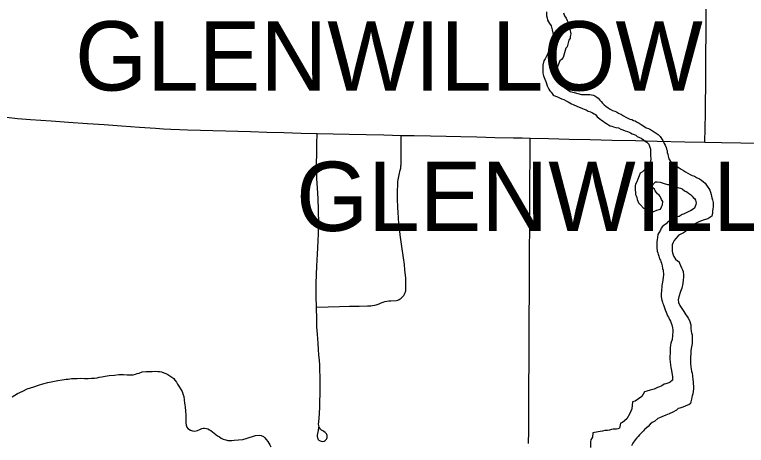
# Model space of a CAD drawing. Extents: x 0 to 34, y 0 to 22.
# Drawn here: x 6.666 to 7.666, y 15.413 to 16.002 of the extents above; entities that cross this region are included whole.
import ezdxf

# ---------------------------------------------------------------- set-up
doc = ezdxf.new("R2010")
doc.units = 0
for name, color, linetype in [('GM_X_City_Street', 7, 'Continuous'), ('GM_X_Corporation_Text', 7, 'Continuous'), ('GM_X_County_Road', 7, 'Continuous'), ('GM_X_Minor_River', 7, 'Continuous')]:
    doc.layers.add(name, color=color, linetype=linetype)

msp = doc.modelspace()

# ---------------------------------------------------------------- linework, layer by layer
at = {"layer": 'GM_X_City_Street'}
for points in [[(7.0813, 15.4379), (7.0805, 15.4333), (7.0797, 15.4293), (7.0794, 15.4273), (7.0793, 15.4257), (7.0796, 15.4234), (7.0801, 15.4223), (7.0807, 15.4213), (7.0815, 15.4204), (7.0825, 15.4197), (7.0835, 15.4192), (7.0846, 15.4188), (7.087, 15.4187), (7.0887, 15.4191), (7.0902, 15.42), (7.0911, 15.4208), (7.0919, 15.4217), (7.0924, 15.4228), (7.0928, 15.4239), (7.0929, 15.4245), (7.093, 15.4256), (7.0928, 15.4269), (7.0925, 15.428), (7.0919, 15.4291), (7.0912, 15.4301), (7.09, 15.431), (7.0882, 15.432), (7.0868, 15.4329), (7.0853, 15.4339), (7.0839, 15.4353), (7.0821, 15.4379), (7.0815, 15.4401), (7.0813, 15.4426), (7.0814, 15.4447), (7.0823, 15.4566), (7.0828, 15.4652), (7.0831, 15.4709), (7.0834, 15.486), (7.0833, 15.5071), (7.083, 15.5159), (7.0827, 15.5228), (7.0823, 15.5297), (7.0817, 15.5366), (7.0811, 15.5445), (7.0805, 15.5524), (7.0796, 15.5653), (7.0793, 15.5703), (7.079, 15.5752), (7.0788, 15.5802), (7.0786, 15.5851), (7.0782, 15.6023), (7.078, 15.6172), (7.0781, 15.6346), (7.0785, 15.6469), (7.0788, 15.6583), (7.0796, 15.6744), (7.0808, 15.6925), (7.0811, 15.7032), (7.0814, 15.7161), (7.0812, 15.7347), (7.0806, 15.7509), (7.0797, 15.7647), (7.0789, 15.778), (7.0787, 15.7831), (7.0785, 15.7996), (7.0786, 15.811), (7.079, 15.8251), (7.0792, 15.8396)], [(7.0782, 15.6023), (7.0945, 15.6026), (7.1098, 15.603), (7.1237, 15.6033), (7.1369, 15.6035), (7.1479, 15.6038), (7.1525, 15.604), (7.1551, 15.6043), (7.1576, 15.6047), (7.16, 15.6054), (7.1626, 15.6062), (7.164, 15.6067), (7.1667, 15.6079), (7.1693, 15.6089), (7.1719, 15.6097), (7.1746, 15.6103), (7.1774, 15.6107), (7.1802, 15.611), (7.1877, 15.6114), (7.1895, 15.6119), (7.1912, 15.6126), (7.1927, 15.6134), (7.1941, 15.6144), (7.1954, 15.6156), (7.1966, 15.6169), (7.1976, 15.6182), (7.1985, 15.6197), (7.1993, 15.6213), (7.1999, 15.6229), (7.2003, 15.6246), (7.2006, 15.6263), (7.2007, 15.6282), (7.2006, 15.6341), (7.2003, 15.6416), (7.1993, 15.653), (7.1986, 15.6603), (7.1975, 15.6694), (7.1952, 15.6852), (7.1929, 15.701), (7.1917, 15.7107), (7.1913, 15.7145), (7.1909, 15.7183), (7.1906, 15.7222), (7.1903, 15.726), (7.19, 15.7298), (7.1895, 15.7402), (7.1893, 15.7485), (7.1893, 15.7614), (7.1894, 15.7696), (7.1895, 15.7717), (7.1898, 15.7739), (7.1902, 15.776), (7.1916, 15.7829), (7.1929, 15.7895), (7.1932, 15.7908), (7.1935, 15.7923), (7.1937, 15.7937), (7.1939, 15.7952), (7.194, 15.7967), (7.194, 15.7981), (7.194, 15.837)], [(7.3685, 15.4159), (7.3686, 15.4328), (7.3687, 15.4557), (7.3688, 15.4748), (7.3689, 15.5001), (7.369, 15.5224), (7.3691, 15.5465), (7.3692, 15.5695), (7.3694, 15.5942), (7.3695, 15.6158), (7.3696, 15.6367), (7.3697, 15.6626), (7.3698, 15.6852), (7.3699, 15.7059), (7.3701, 15.7291), (7.3702, 15.7542), (7.3703, 15.7785), (7.3704, 15.8023), (7.3706, 15.8332)]]:
    msp.add_lwpolyline(points, dxfattribs=at)
at = {"layer": 'GM_X_County_Road'}
for points in [[(7.6096, 15.8275), (7.6099, 15.847), (7.6102, 15.8671), (7.6104, 15.884), (7.6106, 15.9018), (7.6107, 15.9168), (7.6108, 15.9264), (7.6109, 15.9342), (7.611, 15.954), (7.6112, 15.97), (7.6113, 15.986), (7.6114, 15.9993), (7.6114, 16.0097)], [(6.6543, 15.862), (6.6695, 15.8601), (6.6874, 15.8588), (6.7155, 15.8569), (6.7393, 15.8552), (6.7651, 15.8534), (6.788, 15.8518), (6.8116, 15.8501), (6.8365, 15.8484), (6.8583, 15.8468), (6.8691, 15.8461), (6.8793, 15.8455), (6.891, 15.8449), (6.902, 15.8445), (6.9198, 15.844), (6.9365, 15.8436), (6.9542, 15.8431), (6.9706, 15.8426), (6.9882, 15.8421), (7.0103, 15.8415), (7.0336, 15.8409), (7.0573, 15.8402), (7.0792, 15.8396), (7.1013, 15.8391), (7.1231, 15.8386), (7.1461, 15.8381), (7.1705, 15.8376), (7.194, 15.837), (7.2117, 15.8367), (7.2344, 15.8362), (7.2556, 15.8357), (7.2756, 15.8353), (7.2974, 15.8348), (7.3223, 15.8343), (7.3476, 15.8337), (7.3596, 15.8335)], [(7.3596, 15.8335), (7.3706, 15.8332), (7.3954, 15.8326), (7.4238, 15.832), (7.4526, 15.8313), (7.4825, 15.8305), (7.5148, 15.8298), (7.5443, 15.8291), (7.5819, 15.8282), (7.6096, 15.8275), (7.6321, 15.8271), (7.6587, 15.8267), (7.6839, 15.8263)]]:
    msp.add_lwpolyline(points, dxfattribs=at)
at = {"layer": 'GM_X_Minor_River'}
for points in [[(7.393, 16.0059), (7.393, 16.0006), (7.3938, 15.9976), (7.3941, 15.9945), (7.3957, 15.9923), (7.3972, 15.99), (7.3991, 15.9869), (7.4006, 15.9812), (7.4029, 15.971), (7.4029, 15.9679), (7.4014, 15.9649), (7.3999, 15.9611), (7.3983, 15.9569), (7.3964, 15.9543), (7.3957, 15.9516), (7.3945, 15.9489), (7.3934, 15.9463), (7.3911, 15.9417), (7.3892, 15.9387), (7.3881, 15.933), (7.3877, 15.9311), (7.3877, 15.9284), (7.3877, 15.9254), (7.3881, 15.922), (7.3889, 15.9182), (7.3896, 15.9159), (7.3904, 15.914), (7.3919, 15.9106), (7.3927, 15.9079), (7.3938, 15.9049), (7.3949, 15.903), (7.3961, 15.9003), (7.3976, 15.898), (7.3991, 15.8961), (7.4006, 15.8942), (7.4022, 15.8919), (7.4052, 15.8904), (7.4079, 15.8897), (7.4105, 15.8882), (7.4136, 15.887), (7.4166, 15.8859), (7.4197, 15.8844), (7.4227, 15.8828), (7.425, 15.8817), (7.4273, 15.8802), (7.4295, 15.8794), (7.4345, 15.8771), (7.4421, 15.8737), (7.4444, 15.873), (7.447, 15.8718), (7.4501, 15.8703), (7.4531, 15.8692), (7.4558, 15.8677), (7.4581, 15.8665), (7.46, 15.8654), (7.4622, 15.8623), (7.466, 15.8597), (7.4683, 15.8578), (7.4706, 15.8563), (7.4725, 15.8547), (7.4748, 15.8532), (7.4778, 15.8513), (7.4801, 15.8502), (7.4824, 15.8494), (7.4847, 15.8487), (7.4877, 15.8479), (7.4915, 15.8471), (7.4946, 15.8456), (7.4972, 15.8445), (7.5006, 15.8433), (7.5037, 15.8422), (7.506, 15.8415), (7.5079, 15.8403), (7.5101, 15.8392), (7.5128, 15.8384), (7.5151, 15.8373), (7.517, 15.8354), (7.52, 15.8339), (7.5223, 15.8331), (7.5254, 15.8308), (7.528, 15.8289), (7.5299, 15.8278), (7.533, 15.8251), (7.5341, 15.8209), (7.5349, 15.8183)], [(7.4162, 16.0044), (7.4177, 16.0003), (7.4196, 15.9972), (7.4211, 15.9942), (7.4223, 15.9911), (7.4234, 15.9885), (7.4261, 15.9759), (7.4253, 15.9721), (7.4253, 15.9699), (7.4234, 15.9672), (7.4227, 15.9634), (7.4211, 15.9581), (7.4192, 15.9562), (7.4177, 15.9497), (7.4158, 15.9436), (7.4132, 15.9406)], [(7.4132, 15.9406), (7.4113, 15.9387), (7.4101, 15.9364), (7.4082, 15.9322), (7.4071, 15.9277), (7.4067, 15.9246), (7.4063, 15.9212), (7.4067, 15.9182), (7.4075, 15.9159), (7.409, 15.9125), (7.4113, 15.9091), (7.4143, 15.9053), (7.4181, 15.9018), (7.4219, 15.8992), (7.4254, 15.8969), (7.4307, 15.8954), (7.4356, 15.8942), (7.4406, 15.8931), (7.4523, 15.8927), (7.4546, 15.8923), (7.4573, 15.892), (7.4592, 15.8912), (7.4615, 15.8893), (7.4634, 15.8878), (7.466, 15.8851), (7.4676, 15.8832), (7.4695, 15.881), (7.4717, 15.8787), (7.474, 15.8768), (7.4774, 15.8745), (7.4801, 15.873), (7.4831, 15.8711), (7.4862, 15.8699), (7.4888, 15.8692), (7.4915, 15.8673), (7.4953, 15.8654), (7.498, 15.8639), (7.5014, 15.862), (7.5041, 15.8605), (7.5067, 15.8593), (7.5094, 15.8586), (7.512, 15.8574), (7.5143, 15.8567), (7.517, 15.8551), (7.5196, 15.8536), (7.5223, 15.8517), (7.5261, 15.8494), (7.5291, 15.8475), (7.5322, 15.8464), (7.5352, 15.8449), (7.5379, 15.8434), (7.5402, 15.8418), (7.5428, 15.8399), (7.5455, 15.838), (7.5482, 15.8354), (7.5501, 15.8327), (7.552, 15.8301), (7.5539, 15.8259), (7.5554, 15.8236), (7.5565, 15.8206), (7.5569, 15.8183), (7.5577, 15.8164), (7.558, 15.8137), (7.5588, 15.8115), (7.5592, 15.8084), (7.5603, 15.805), (7.5619, 15.8023), (7.5676, 15.7963), (7.5698, 15.7951), (7.5721, 15.794), (7.5744, 15.7925), (7.5771, 15.7909), (7.5801, 15.789), (7.5831, 15.7871), (7.5862, 15.7852), (7.5892, 15.7833), (7.5923, 15.7822), (7.5953, 15.7811), (7.598, 15.7796), (7.6022, 15.7777), (7.6048, 15.7758), (7.6075, 15.7735), (7.6098, 15.7716), (7.6117, 15.7689), (7.6136, 15.7663), (7.6151, 15.7644), (7.6162, 15.7621), (7.617, 15.7594), (7.6181, 15.756), (7.6189, 15.7518), (7.62, 15.7488), (7.6208, 15.745), (7.6208, 15.7419), (7.6208, 15.7397), (7.6204, 15.7359), (7.62, 15.734), (7.62, 15.7309), (7.6189, 15.7264), (7.6136, 15.7229), (7.6086, 15.7214), (7.6048, 15.7203)], [(7.5349, 15.8183), (7.5349, 15.8164), (7.5349, 15.8133), (7.5352, 15.8103), (7.5356, 15.8042), (7.5349, 15.8016), (7.5345, 15.7993), (7.533, 15.797), (7.5303, 15.7928), (7.528, 15.7909), (7.5242, 15.7871), (7.5208, 15.7852), (7.5197, 15.7818), (7.5178, 15.7772), (7.5163, 15.7734), (7.5144, 15.7704), (7.514, 15.7681), (7.514, 15.7636), (7.514, 15.7617), (7.5144, 15.7594), (7.5147, 15.7563), (7.5155, 15.7544), (7.5163, 15.7522), (7.517, 15.7495), (7.5189, 15.7446), (7.5216, 15.7419), (7.5254, 15.7377), (7.5281, 15.7366), (7.53, 15.7354), (7.5326, 15.7339), (7.5353, 15.7332), (7.5372, 15.7328), (7.5395, 15.7328), (7.5436, 15.7347), (7.5471, 15.7358), (7.549, 15.7362), (7.5501, 15.7393), (7.5516, 15.7419), (7.552, 15.7465), (7.5501, 15.7495), (7.5493, 15.7514), (7.5482, 15.7533), (7.5471, 15.7552), (7.5448, 15.7571), (7.5433, 15.759), (7.5417, 15.7613), (7.5406, 15.7636), (7.5383, 15.7655), (7.5379, 15.7681), (7.5391, 15.7708), (7.5421, 15.7734), (7.5444, 15.7735), (7.5482, 15.7731), (7.5539, 15.7712), (7.5584, 15.77), (7.5611, 15.7697), (7.5642, 15.7685), (7.5668, 15.7678), (7.5695, 15.767), (7.5714, 15.7662), (7.574, 15.7655), (7.5763, 15.7647), (7.5782, 15.764), (7.5816, 15.7613), (7.5847, 15.7598), (7.5873, 15.7579), (7.5896, 15.756), (7.5923, 15.7541), (7.5934, 15.7522), (7.5953, 15.7507), (7.5968, 15.7484), (7.5972, 15.7465), (7.5976, 15.7442), (7.5972, 15.7423), (7.5953, 15.7374), (7.5923, 15.7351), (7.5896, 15.7339), (7.5874, 15.7328), (7.5839, 15.7309), (7.5801, 15.7294), (7.5782, 15.729), (7.5744, 15.7263), (7.5714, 15.7256), (7.5691, 15.7241), (7.5661, 15.7229), (7.5642, 15.7225), (7.5608, 15.7195), (7.5589, 15.7187), (7.5566, 15.7161), (7.5539, 15.7142), (7.5516, 15.7123), (7.5497, 15.71), (7.5486, 15.7073), (7.5463, 15.7039), (7.5452, 15.7013), (7.5444, 15.694), (7.5437, 15.6918), (7.5437, 15.6876), (7.544, 15.6838), (7.5444, 15.6788), (7.5452, 15.6766)], [(7.6048, 15.7203), (7.6014, 15.7188), (7.5976, 15.7172), (7.5938, 15.715), (7.5908, 15.7123), (7.5874, 15.71), (7.5855, 15.7092), (7.5851, 15.7073), (7.5828, 15.7054), (7.5801, 15.7039), (7.5748, 15.7009), (7.5729, 15.6997), (7.5699, 15.6959), (7.5676, 15.6933), (7.5661, 15.6906), (7.5649, 15.6872), (7.5646, 15.6834), (7.5646, 15.6807), (7.5646, 15.6788), (7.5653, 15.6762), (7.5661, 15.6739), (7.5672, 15.6716), (7.5691, 15.6678), (7.5722, 15.6655), (7.5741, 15.664), (7.5748, 15.6621), (7.576, 15.6591), (7.5775, 15.656), (7.579, 15.6534), (7.5798, 15.6507), (7.5802, 15.6465), (7.5802, 15.6431), (7.5798, 15.6397), (7.5794, 15.6344), (7.5779, 15.6283), (7.576, 15.6237), (7.5737, 15.6161), (7.573, 15.6123), (7.5733, 15.6085), (7.5752, 15.6044), (7.5772, 15.6017), (7.5787, 15.599), (7.5806, 15.5964), (7.5821, 15.5941), (7.5836, 15.5918), (7.5851, 15.5892), (7.5867, 15.5869), (7.5886, 15.5839), (7.5901, 15.5778), (7.5901, 15.5736), (7.5909, 15.569), (7.5912, 15.5671), (7.592, 15.5641), (7.592, 15.5614), (7.592, 15.558), (7.592, 15.555), (7.592, 15.5523), (7.5916, 15.55), (7.5912, 15.5478), (7.5905, 15.5428), (7.5901, 15.5398), (7.5901, 15.5379), (7.5897, 15.5348), (7.5897, 15.5318), (7.5897, 15.5295), (7.5897, 15.5246), (7.5901, 15.5208), (7.5909, 15.5174), (7.5913, 15.5147), (7.592, 15.5117), (7.5924, 15.5082), (7.5932, 15.5029), (7.5935, 15.5003), (7.5935, 15.498), (7.5939, 15.4938), (7.5939, 15.4904), (7.5928, 15.4835), (7.592, 15.4809), (7.5917, 15.479), (7.5913, 15.4763), (7.5905, 15.4729), (7.5898, 15.4706), (7.5875, 15.4687), (7.5856, 15.4683), (7.5795, 15.4653), (7.5753, 15.4642), (7.573, 15.4634), (7.5708, 15.4615), (7.5658, 15.4584), (7.5605, 15.4565), (7.5559, 15.4543), (7.5506, 15.4524), (7.5472, 15.4508), (7.5453, 15.4501), (7.5411, 15.4463), (7.5373, 15.4444), (7.5347, 15.4421), (7.532, 15.4391), (7.5293, 15.4368), (7.5271, 15.4349), (7.5255, 15.433)], [(7.5452, 15.6766), (7.5456, 15.6747), (7.5463, 15.672), (7.5475, 15.6682), (7.5486, 15.6663), (7.5494, 15.6644), (7.5501, 15.6625), (7.5505, 15.6606), (7.5513, 15.6587), (7.5517, 15.6549), (7.5524, 15.6526), (7.5528, 15.6462), (7.5524, 15.6427), (7.5517, 15.6363), (7.5505, 15.6317), (7.5502, 15.6237), (7.5498, 15.6211), (7.5498, 15.6161), (7.5502, 15.6142), (7.5505, 15.6116), (7.5517, 15.6089), (7.5521, 15.607), (7.5528, 15.6051), (7.554, 15.6025), (7.5551, 15.5983), (7.5566, 15.5952), (7.5574, 15.593), (7.5585, 15.5903), (7.5597, 15.5884), (7.5612, 15.5854), (7.5623, 15.5831), (7.5635, 15.5804), (7.5642, 15.5778), (7.565, 15.574), (7.5658, 15.5713), (7.5658, 15.569), (7.5654, 15.5633), (7.5646, 15.558), (7.5631, 15.5527), (7.5624, 15.55), (7.562, 15.5466), (7.562, 15.5394), (7.5616, 15.5348), (7.5616, 15.5314), (7.562, 15.5268), (7.5631, 15.5196), (7.5639, 15.5154), (7.5654, 15.5071), (7.565, 15.5025), (7.562, 15.4995), (7.5601, 15.4987), (7.5559, 15.4972), (7.554, 15.4968), (7.5506, 15.4945), (7.5476, 15.493), (7.5445, 15.4923), (7.54, 15.49), (7.5346, 15.4885), (7.5301, 15.4873), (7.527, 15.4866), (7.5232, 15.4801), (7.5141, 15.4736), (7.5103, 15.4725), (7.5096, 15.463), (7.5069, 15.4569), (7.5027, 15.4497), (7.497, 15.4444), (7.494, 15.4436), (7.4925, 15.4368), (7.4906, 15.4356), (7.4887, 15.4352), (7.4864, 15.4352), (7.4841, 15.4352), (7.4818, 15.4349), (7.4792, 15.4341), (7.4761, 15.4337), (7.4727, 15.4333), (7.4693, 15.4326), (7.4662, 15.4322), (7.4636, 15.4318), (7.4613, 15.4314), (7.4586, 15.4307), (7.4564, 15.4303), (7.4556, 15.4242), (7.4537, 15.4208), (7.4529, 15.4181), (7.4529, 15.4105)], [(6.7041, 15.4972), (6.7109, 15.4991), (6.7178, 15.5007), (6.7246, 15.5018), (6.7307, 15.5029), (6.736, 15.5037), (6.7387, 15.5037), (6.741, 15.5041), (6.7432, 15.5048), (6.7463, 15.5048), (6.7512, 15.5045), (6.7562, 15.5049), (6.7611, 15.5045), (6.766, 15.5045), (6.7706, 15.5049), (6.7748, 15.5052), (6.7782, 15.5056), (6.7813, 15.5064), (6.7847, 15.5071), (6.7892, 15.5079), (6.7946, 15.5087), (6.8022, 15.5094), (6.8082, 15.5102), (6.8143, 15.5102), (6.8193, 15.5098), (6.8231, 15.5098), (6.8257, 15.5098), (6.8276, 15.5098), (6.831, 15.5106), (6.8329, 15.5113), (6.836, 15.5121), (6.8398, 15.5136), (6.8455, 15.5144), (6.8493, 15.5144), (6.8535, 15.5144), (6.858, 15.5148), (6.8614, 15.5144), (6.8637, 15.514), (6.8664, 15.5136), (6.8694, 15.5125), (6.8725, 15.5114), (6.8751, 15.5102), (6.8831, 15.5045), (6.8846, 15.5022), (6.8869, 15.4996), (6.8884, 15.4969), (6.8903, 15.4943), (6.8922, 15.4905), (6.8945, 15.487), (6.8957, 15.4836), (6.8968, 15.4798), (6.8972, 15.4756), (6.898, 15.4707), (6.8983, 15.4684), (6.8987, 15.4661), (6.8987, 15.4639), (6.8991, 15.4616), (6.8991, 15.4589), (6.8995, 15.4555), (6.8995, 15.4513), (6.8995, 15.4479), (6.8995, 15.4441), (6.9003, 15.4407), (6.901, 15.438), (6.9025, 15.4361), (6.906, 15.4339), (6.9086, 15.4331), (6.9117, 15.4327), (6.9139, 15.4331), (6.9158, 15.4335), (6.9196, 15.4354), (6.9215, 15.4361), (6.9234, 15.4369), (6.9253, 15.4369), (6.928, 15.4361), (6.9299, 15.4358), (6.9318, 15.4346), (6.9337, 15.4335), (6.936, 15.4316), (6.9383, 15.4301), (6.9406, 15.4282), (6.9428, 15.4263), (6.9455, 15.4248), (6.9478, 15.4229), (6.9508, 15.4217), (6.9542, 15.4206), (6.9573, 15.4198), (6.9599, 15.4198), (6.9626, 15.4198), (6.9656, 15.4202), (6.9778, 15.4213), (6.982, 15.4225), (6.9862, 15.424), (6.9907, 15.4255), (6.9949, 15.4267), (7.0002, 15.4271), (7.0025, 15.4267), (7.0059, 15.4252), (7.0078, 15.4233), (7.0097, 15.421), (7.0116, 15.4183)], [(6.6623, 15.4794), (6.6695, 15.4839), (6.6767, 15.4873), (6.6828, 15.4904), (6.6916, 15.493), (6.698, 15.4953), (6.7041, 15.4972)], [(7.5255, 15.433), (7.5229, 15.4303), (7.5202, 15.4276), (7.5183, 15.4254), (7.5164, 15.4235), (7.5141, 15.4208), (7.5111, 15.4162), (7.5092, 15.4124)], [(7.0116, 15.4183), (7.0132, 15.4164), (7.0147, 15.4141), (7.0158, 15.4111)]]:
    msp.add_lwpolyline(points, dxfattribs=at)

# ---------------------------------------------------------------- texts
at = {"layer": 'GM_X_Corporation_Text'}
for p in [(6.7482, 15.8983), (7.0505, 15.7063)]:
    msp.add_text('GLENWILLOW', height=0.0947, rotation=0, dxfattribs=at).set_placement(p)

doc.saveas('drawing.dxf')
